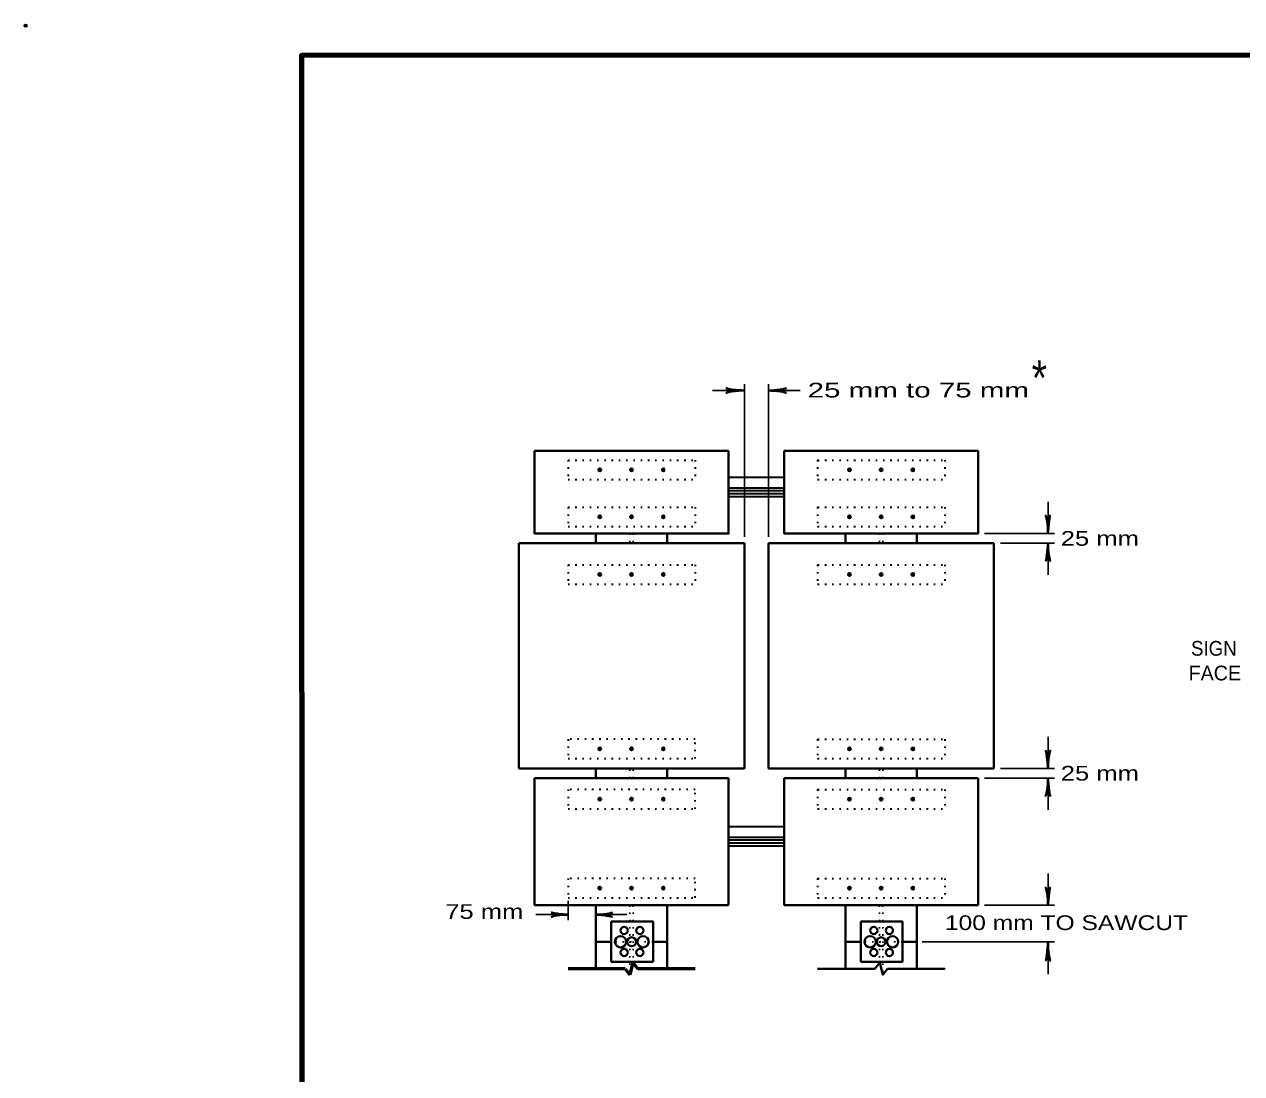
# Model space of a CAD drawing. Extents: x 851 to 1706, y -23 to 521.
# Drawn here: x 850.8 to 1102.1, y 303.9 to 520.6 of the extents above; entities that cross this region are included whole.
import ezdxf
from ezdxf.enums import TextEntityAlignment as Align

# ---------------------------------------------------------------- set-up
doc = ezdxf.new("R2010")
doc.units = 0
doc.header["$PDMODE"] = 32
doc.header["$PDSIZE"] = 0.5
doc.linetypes.add('DOTTED', pattern=[1.5, 0.3, -1.2])
doc.layers.add('1', color=7, linetype='Continuous', lineweight=35)

msp = doc.modelspace()

# ---------------------------------------------------------------- hatches: boundary and pattern name
at = {"layer": '1'}
for points in [[(969.881, 428.632, 1), (969.309, 428.632, 1)], [(976.442, 428.632, 1), (975.87, 428.632, 1)], [(983.003, 428.632, 1), (982.431, 428.632, 1)], [(1021.412, 428.632, 1), (1020.84, 428.632, 1)], [(1027.973, 428.632, 1), (1027.401, 428.632, 1)], [(1034.534, 428.632, 1), (1033.962, 428.632, 1)], [(969.881, 418.9, 1), (969.309, 418.9, 1)], [(976.442, 418.9, 1), (975.87, 418.9, 1)], [(983.003, 418.9, 1), (982.431, 418.9, 1)], [(1021.412, 418.9, 1), (1020.84, 418.9, 1)], [(1027.973, 418.9, 1), (1027.401, 418.9, 1)], [(1034.534, 418.9, 1), (1033.962, 418.9, 1)], [(969.881, 407.008, 1), (969.309, 407.008, 1)], [(976.442, 407.008, 1), (975.87, 407.008, 1)], [(983.003, 407.008, 1), (982.431, 407.008, 1)], [(1021.412, 407.008, 1), (1020.84, 407.008, 1)], [(1027.973, 407.008, 1), (1027.401, 407.008, 1)], [(1034.534, 407.008, 1), (1033.962, 407.008, 1)], [(969.881, 370.977, 1), (969.309, 370.977, 1)], [(976.442, 370.977, 1), (975.87, 370.977, 1)], [(983.003, 370.977, 1), (982.431, 370.977, 1)], [(1021.412, 370.977, 1), (1020.84, 370.977, 1)], [(1027.973, 370.977, 1), (1027.401, 370.977, 1)], [(1034.534, 370.977, 1), (1033.962, 370.977, 1)], [(969.881, 360.589, 1), (969.309, 360.589, 1)], [(976.442, 360.589, 1), (975.87, 360.589, 1)], [(983.003, 360.589, 1), (982.431, 360.589, 1)], [(1021.412, 360.589, 1), (1020.84, 360.589, 1)], [(1027.973, 360.589, 1), (1027.401, 360.589, 1)], [(1034.534, 360.589, 1), (1033.962, 360.589, 1)], [(969.881, 342.232, 1), (969.309, 342.232, 1)], [(976.442, 342.232, 1), (975.87, 342.232, 1)], [(983.003, 342.232, 1), (982.431, 342.232, 1)], [(1021.412, 342.218, 1), (1020.84, 342.218, 1)], [(1027.973, 342.218, 1), (1027.401, 342.218, 1)], [(1034.534, 342.218, 1), (1033.962, 342.218, 1)]]:
    msp.add_hatch(color=256, dxfattribs=at).paths.add_polyline_path(points)

# ---------------------------------------------------------------- linework, layer by layer
at = {"layer": '1', "lineweight": 25}
for p, q in [((992.859, 444.98), (999.42, 444.98)), ((999.448, 414.799), (999.448, 446.292)), ((1004.396, 414.799), (1004.396, 446.292)), ((1004.396, 444.98), (1010.957, 444.98)), ((1062.132, 415.456), (1062.132, 422.017)), ((1049.01, 415.456), (1063.445, 415.456)), ((1052.291, 413.487), (1063.445, 413.487)), ((1062.132, 413.487), (1062.132, 406.926)), ((1062.132, 366.904), (1062.132, 373.465)), ((1049.01, 364.936), (1063.445, 364.936)), ((1052.291, 366.904), (1063.445, 366.904)), ((1062.132, 364.936), (1062.132, 358.375)), ((1062.132, 338.665), (1062.132, 345.226)), ((963.034, 339.616), (963.034, 335.622)), ((1049.01, 338.692), (1063.445, 338.692)), ((956.361, 336.743), (963.034, 336.743)), ((968.775, 336.743), (975.169, 336.743)), ((1036.162, 331.147), (1063.445, 331.147)), ((1062.132, 324.422), (1062.132, 330.983))]:
    msp.add_line(p, q, dxfattribs=at)
at = {"layer": '1', "linetype": 'DOTTED'}
for p, q in [((963.034, 430.628), (989.278, 430.628)), ((963.034, 430.628), (963.034, 426.637)), ((989.278, 430.628), (989.278, 426.637)), ((1014.565, 430.628), (1040.809, 430.628)), ((1014.565, 430.628), (1014.565, 426.637)), ((1040.809, 430.628), (1040.809, 426.637)), ((963.034, 426.637), (989.278, 426.637)), ((1014.565, 426.637), (1040.809, 426.637)), ((963.034, 420.896), (989.278, 420.896)), ((963.034, 420.896), (963.034, 416.904)), ((989.278, 420.896), (989.278, 416.904)), ((1014.565, 420.896), (1040.809, 420.896)), ((1014.565, 420.896), (1014.565, 416.904)), ((1040.809, 420.896), (1040.809, 416.904)), ((963.034, 416.904), (989.278, 416.904)), ((1014.565, 416.904), (1040.809, 416.904)), ((963.034, 409.004), (989.278, 409.004)), ((963.034, 409.004), (963.034, 405.013)), ((989.278, 409.004), (989.278, 405.013)), ((1014.565, 409.004), (1040.809, 409.004)), ((1014.565, 409.004), (1014.565, 405.013)), ((1040.809, 409.004), (1040.809, 405.013)), ((963.034, 405.013), (989.278, 405.013)), ((1014.565, 405.013), (1040.809, 405.013)), ((1014.565, 372.973), (1040.809, 372.973)), ((1014.565, 372.973), (1014.565, 368.982)), ((1040.809, 372.973), (1040.809, 368.982)), ((1014.565, 368.982), (1040.809, 368.982)), ((1014.565, 362.585), (1040.809, 362.585)), ((1014.565, 362.585), (1014.565, 358.594)), ((1040.809, 362.585), (1040.809, 358.594)), ((1014.565, 358.594), (1040.809, 358.594)), ((1014.565, 344.214), (1040.809, 344.214)), ((1014.565, 344.214), (1014.565, 340.223)), ((1040.809, 344.214), (1040.809, 340.223)), ((1014.565, 340.223), (1040.809, 340.223))]:
    msp.add_line(p, q, dxfattribs=at)
at = {"layer": '1', "linetype": 'DOTTED', "lineweight": 25}
for p, q in [((1040.809, 430.628), (1040.809, 426.637)), ((975.828, 415.456), (975.828, 413.487)), ((976.484, 415.456), (976.484, 413.487)), ((1027.359, 415.456), (1027.359, 413.487)), ((1028.015, 415.456), (1028.015, 413.487)), ((1040.809, 372.973), (1040.809, 368.982)), ((975.828, 364.936), (975.828, 366.904)), ((976.484, 364.936), (976.484, 366.904)), ((1027.359, 364.936), (1027.359, 366.904)), ((1028.015, 364.936), (1028.015, 366.904)), ((1040.809, 362.585), (1040.809, 358.594)), ((1040.809, 344.214), (1040.809, 340.25)), ((1040.809, 344.214), (1040.809, 340.223)), ((975.828, 338.692), (975.828, 324.23)), ((976.484, 338.692), (976.484, 326.8)), ((1027.359, 338.692), (1027.359, 326.8)), ((1028.015, 338.692), (1028.015, 324.34)), ((980.612, 331.147), (971.973, 331.147)), ((1032.116, 331.147), (1023.477, 331.147))]:
    msp.add_line(p, q, dxfattribs=at)
at = {"layer": '1'}
for p, q in [((996.167, 427.074), (1007.676, 427.074)), ((996.167, 424.86), (1007.676, 424.86)), ((1007.676, 424.258), (996.167, 424.258)), ((1007.676, 423.657), (996.167, 423.657)), ((996.167, 423.083), (1007.676, 423.083)), ((996.167, 354.958), (1007.676, 354.958)), ((996.167, 352.743), (1007.676, 352.743)), ((1007.676, 352.142), (996.167, 352.142)), ((1007.676, 351.513), (996.167, 351.513)), ((996.167, 350.966), (1007.676, 350.966))]:
    msp.add_line(p, q, dxfattribs=at)
at = {"layer": '1', "lineweight": 40}
for p, q in [((968.775, 415.456), (968.775, 413.487)), ((983.537, 415.456), (983.537, 413.487)), ((1020.306, 415.456), (1020.306, 413.487)), ((1035.068, 415.456), (1035.068, 413.487)), ((952.865, 413.487), (999.448, 413.487)), ((952.865, 413.487), (952.865, 366.904)), ((999.448, 413.487), (999.448, 366.904)), ((1050.979, 413.487), (1004.396, 413.487)), ((1004.396, 413.487), (1004.396, 366.904)), ((1050.979, 413.487), (1050.979, 366.904)), ((952.865, 366.904), (999.448, 366.904)), ((956.145, 364.936), (996.167, 364.936)), ((956.145, 338.692), (956.145, 364.936)), ((968.775, 364.936), (968.775, 366.904)), ((983.537, 364.936), (983.537, 366.904)), ((996.167, 364.936), (996.167, 338.692)), ((1050.979, 366.904), (1004.396, 366.904)), ((1047.698, 364.936), (1007.676, 364.936)), ((1007.676, 364.936), (1007.676, 338.692)), ((1020.306, 364.936), (1020.306, 366.904)), ((1035.068, 364.936), (1035.068, 366.904)), ((1047.698, 338.692), (1047.698, 364.936)), ((956.145, 338.692), (996.167, 338.692)), ((968.775, 338.692), (968.775, 325.57)), ((983.537, 338.692), (983.537, 325.57)), ((1047.698, 338.692), (1007.676, 338.692)), ((1020.306, 338.692), (1020.306, 325.57)), ((1035.068, 338.692), (1035.068, 325.57)), ((980.612, 335.357), (971.973, 335.357)), ((971.973, 335.357), (971.973, 326.991)), ((980.612, 335.357), (980.612, 326.991)), ((1023.477, 335.357), (1023.477, 326.991)), ((1032.116, 335.357), (1023.477, 335.357)), ((1032.116, 335.357), (1032.116, 326.991)), ((971.973, 331.147), (968.775, 331.147)), ((980.612, 331.147), (983.537, 331.147)), ((1023.477, 331.147), (1020.306, 331.147)), ((1032.116, 331.147), (1035.068, 331.147)), ((980.612, 326.991), (971.973, 326.991)), ((1032.116, 326.991), (1023.477, 326.991))]:
    msp.add_line(p, q, dxfattribs=at)
at = {"layer": '1', "lineweight": 53}
for p, q in [((976.429, 326.855), (975.828, 324.34)), ((976.429, 326.855), (977.468, 325.57)), ((974.844, 325.57), (963.034, 325.57)), ((974.844, 325.57), (975.828, 324.34)), ((989.278, 325.57), (977.468, 325.57))]:
    msp.add_line(p, q, dxfattribs=at)
at = {"layer": '1', "lineweight": 158}
msp.add_lwpolyline([(1699.744, 514.252), (908.044, 514.152), (908.144, -11.848)], dxfattribs=at)
at = {"layer": '1', "lineweight": 40}
for points in [[(996.167, 432.514), (956.145, 432.514), (956.145, 415.456), (996.167, 415.456)], [(1007.676, 432.514), (1047.698, 432.514), (1047.698, 415.456), (1007.676, 415.456)]]:
    msp.add_lwpolyline(points, close=True, dxfattribs=at)
at = {"layer": '1', "linetype": 'DOTTED'}
for points in [[(989.278, 372.973), (963.034, 372.973), (963.034, 368.982), (989.278, 368.982)], [(989.278, 362.585), (963.034, 362.585), (963.034, 358.594), (989.278, 358.594)], [(989.278, 344.214), (963.034, 344.214), (963.034, 340.25), (989.278, 340.25)]]:
    msp.add_lwpolyline(points, close=True, dxfattribs=at)
at = {"layer": '1', "lineweight": 40}
for points in [[(1028.999, 325.57), (1028.015, 324.34), (1027.387, 326.855), (1026.375, 325.57), (1014.565, 325.57)], [(1028.999, 325.57), (1040.809, 325.57), (1028.999, 325.57)]]:
    msp.add_lwpolyline(points, dxfattribs=at)
for centre, radius in [((969.595, 428.632), 0.286), ((976.156, 428.632), 0.286), ((982.717, 428.632), 0.286), ((1021.126, 428.632), 0.286), ((1027.687, 428.632), 0.286), ((1034.248, 428.632), 0.286), ((969.595, 418.9), 0.286), ((976.156, 418.9), 0.286), ((982.717, 418.9), 0.286), ((1021.126, 418.9), 0.286), ((1027.687, 418.9), 0.286), ((1034.248, 418.9), 0.286), ((969.595, 407.008), 0.286), ((976.156, 407.008), 0.286), ((982.717, 407.008), 0.286), ((1021.126, 407.008), 0.286), ((1027.687, 407.008), 0.286), ((1034.248, 407.008), 0.286), ((969.595, 370.977), 0.286), ((976.156, 370.977), 0.286), ((982.717, 370.977), 0.286), ((1021.126, 370.977), 0.286), ((1027.687, 370.977), 0.286), ((1034.248, 370.977), 0.286), ((969.595, 360.589), 0.286), ((976.156, 360.589), 0.286), ((982.717, 360.589), 0.286), ((1021.126, 360.589), 0.286), ((1027.687, 360.589), 0.286), ((1034.248, 360.589), 0.286), ((969.595, 342.232), 0.286), ((976.156, 342.232), 0.286), ((982.717, 342.232), 0.286), ((1021.126, 342.218), 0.286), ((1027.687, 342.218), 0.286), ((1034.248, 342.218), 0.286), ((973.889, 331.165), 1.17), ((974.632, 333.486), 0.745), ((976.161, 331.137), 0.927), ((977.855, 333.486), 0.745), ((978.526, 331.165), 1.17), ((1025.409, 331.165), 1.17), ((1026.152, 333.486), 0.745), ((1027.681, 331.137), 0.927), ((1029.375, 333.486), 0.745), ((1030.046, 331.165), 1.17), ((974.632, 328.949), 0.745), ((977.855, 328.949), 0.745), ((1026.152, 328.949), 0.745), ((1029.375, 328.949), 0.745)]:
    msp.add_circle(centre, radius, dxfattribs=at)
for centre, major_axis, ratio, start_param, end_param in [((997.979, 444.624), (2.343, 0.205), 0.122415, 0.8963533, 3.1415927), ((997.979, 444.624), (2.343, 0.205), 0.122415, 0.8963533, 3.1415927), ((997.94, 445.264), (2.305, -0.23), 0.07063, 3.1407148, 5.41811), ((997.94, 445.264), (2.305, -0.23), 0.07063, 3.1407148, 5.41811), ((1005.815, 445.349), (-2.343, -0.205), 0.122415, 0.8963533, 3.1415927), ((1005.853, 444.708), (-2.305, 0.23), 0.07063, 3.1407148, 5.41811), ((1061.757, 416.893), (0.205, -2.343), 0.122415, 0.8963533, 3.1415927), ((1061.757, 416.893), (0.205, -2.343), 0.122415, 0.8963533, 3.1415927), ((1062.398, 416.932), (-0.23, -2.305), 0.07063, 3.1407148, 5.41811), ((1062.398, 416.932), (-0.23, -2.305), 0.07063, 3.1407148, 5.41811), ((1061.842, 412.023), (0.23, 2.305), 0.07063, 3.1407148, 5.41811), ((1061.842, 412.023), (0.23, 2.305), 0.07063, 3.1407148, 5.41811), ((1062.483, 412.061), (-0.205, 2.343), 0.122415, 0.8963533, 3.1415927), ((1062.483, 412.061), (-0.205, 2.343), 0.122415, 0.8963533, 3.1415927), ((1061.842, 368.38), (0.23, -2.305), 0.07063, 0.8650754, 3.1424706), ((1061.842, 368.38), (0.23, -2.305), 0.07063, 0.8650754, 3.1424706), ((1062.483, 368.342), (-0.205, -2.343), 0.122415, 3.1415927, 5.386832), ((1062.483, 368.342), (-0.205, -2.343), 0.122415, 3.1415927, 5.386832), ((1061.757, 363.51), (0.205, 2.343), 0.122415, 3.1415927, 5.386832), ((1061.757, 363.51), (0.205, 2.343), 0.122415, 3.1415927, 5.386832), ((1062.398, 363.472), (-0.23, 2.305), 0.07063, 0.8650754, 3.1424706), ((1062.398, 363.472), (-0.23, 2.305), 0.07063, 0.8650754, 3.1424706), ((1061.757, 340.086), (0.205, -2.343), 0.122415, 0.8963533, 3.1415927), ((1062.398, 340.124), (-0.23, -2.305), 0.07063, 3.1407148, 5.41811), ((961.689, 336.997), (2.108, -0.211), 0.07063, 3.1407148, 5.41811), ((970.084, 337.074), (-2.143, -0.187), 0.122415, 0.8963533, 3.1415927), ((961.725, 336.411), (2.143, 0.187), 0.122415, 0.8963533, 3.1415927), ((970.12, 336.489), (-2.108, 0.211), 0.07063, 3.1407148, 5.41811), ((1061.842, 329.523), (0.23, 2.305), 0.07063, 3.1407148, 5.41811), ((1062.483, 329.561), (-0.205, 2.343), 0.122415, 0.8963533, 3.1415927)]:
    msp.add_ellipse(centre, major_axis=major_axis, ratio=ratio, start_param=start_param, end_param=end_param, dxfattribs=at)
at = {"layer": '1'}
msp.add_point((851.044, 520.352), dxfattribs=at)

# ---------------------------------------------------------------- texts
for s, height, width, p in [('*', 7.2, 0.85, (1060.348, 444.007)), ('25 mm to 75 mm', 3.037, 1.5, (1035.354, 443.543)), ('25 mm', 3.037, 1.3, (1072.828, 412.925)), ('SIGN', 3.037, 0.95, (1096.367, 390.224)), ('25 mm', 3.037, 1.3, (1072.828, 364.428)), ('75 mm', 3.037, 1.3, (945.751, 335.867)), ('100 mm TO SAWCUT', 3.037, 1.25, (1065.939, 333.565))]:
    msp.add_text(s, height=height, dxfattribs=dict(at, width=width)).set_placement(p, align=Align.CENTER)
msp.add_text('FACE', height=3.037, dxfattribs=at).set_placement((1096.573, 385.122), align=Align.CENTER)

doc.saveas('drawing.dxf')
